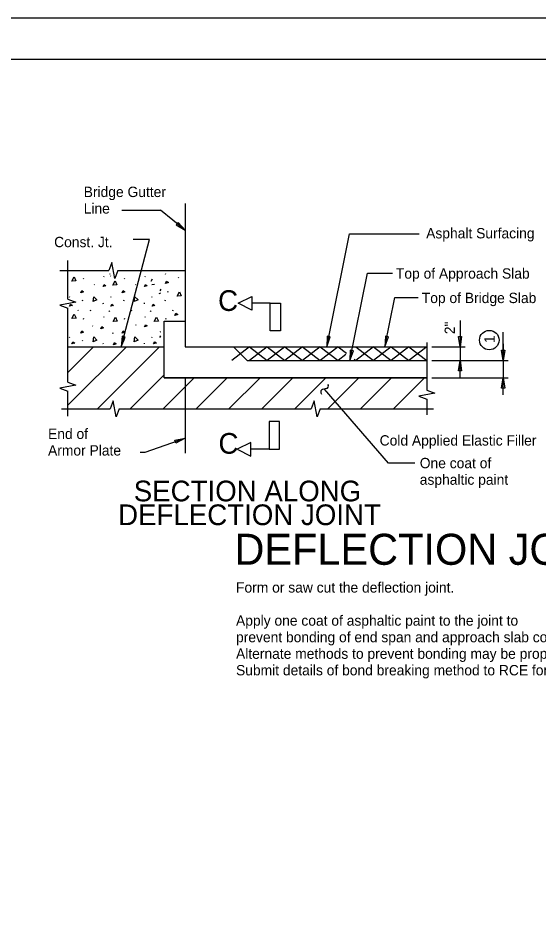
# Model space of a CAD drawing. Extents: x 2799.7 to 2896, y 515.2 to 573.9.
# Drawn here: x 2834.77 to 2851.55, y 544.56 to 573.89 of the extents above; entities that cross this region are included whole.
import ezdxf

# ---------------------------------------------------------------- set-up
doc = ezdxf.new("R2010")
doc.units = 0
for name, color, linetype in [('BR_AUTO DIMENSION', 7, 'Continuous'), ('BR_BORDER LINES', 7, 'Continuous'), ('BR_CONCRETE', 7, 'Continuous'), ('BR_DETAILS', 7, 'Continuous'), ('BR_STRUCTURAL STEEL', 7, 'Continuous'), ('BR_TABLE LINES', 7, 'Continuous'), ('BR_TEXT', 7, 'Continuous'), ('Level 31', 7, 'Continuous')]:
    doc.layers.add(name, color=color, linetype=linetype)

msp = doc.modelspace()

# ---------------------------------------------------------------- linework, layer by layer
at = {"layer": 'BR_AUTO DIMENSION'}
for p, q in [((2840.156, 567.916), (2840.156, 564.596)), ((2838.111, 567.706), (2839.357, 567.706)), ((2840.156, 567.064), (2839.357, 567.706)), ((2838.093, 563.308), (2839.001, 566.763)), ((2839.001, 566.763), (2838.48, 566.763)), ((2844.718, 563.308), (2845.457, 566.948)), ((2845.457, 566.948), (2847.698, 566.948)), ((2845.462, 562.863), (2846.034, 565.678)), ((2846.034, 565.678), (2846.836, 565.678)), ((2846.595, 563.308), (2846.917, 564.891)), ((2846.917, 564.891), (2847.661, 564.891)), ((2849.018, 564.147), (2849.018, 563.308)), ((2849.018, 563.841), (2849.018, 563.308)), ((2850.405, 562.863), (2850.405, 563.774)), ((2848.108, 563.308), (2849.185, 563.308)), ((2849.018, 563.308), (2849.018, 562.863)), ((2850.405, 563.396), (2850.405, 562.863)), ((2848.108, 562.863), (2850.572, 562.863)), ((2848.108, 562.863), (2849.185, 562.863)), ((2849.018, 562.33), (2849.018, 562.863)), ((2850.405, 562.863), (2850.405, 562.308)), ((2844.753, 562.105), (2844.768, 562.074)), ((2848.108, 562.308), (2850.572, 562.308)), ((2850.405, 561.762), (2850.405, 562.308)), ((2850.405, 561.774), (2850.405, 562.308)), ((2844.533, 561.824), (2844.551, 561.782)), ((2844.712, 561.961), (2844.58, 561.924)), ((2846.705, 559.554), (2844.646, 561.943)), ((2838.865, 559.908), (2840.156, 560.359)), ((2838.707, 559.908), (2838.865, 559.908)), ((2847.556, 559.554), (2846.705, 559.554))]:
    msp.add_line(p, q, dxfattribs=at)
for points in [[(2839.865, 567.234), (2840.156, 567.064), (2839.928, 567.312)], [(2838.126, 563.643), (2838.093, 563.308), (2838.223, 563.619)], [(2844.735, 563.644), (2844.718, 563.308), (2844.833, 563.624)], [(2846.613, 563.644), (2846.595, 563.308), (2846.711, 563.624)], [(2849.068, 563.641), (2849.018, 563.308), (2848.968, 563.641)], [(2845.479, 563.2), (2845.462, 562.863), (2845.577, 563.18)], [(2850.455, 563.196), (2850.405, 562.863), (2850.355, 563.196)], [(2848.968, 562.53), (2849.018, 562.863), (2849.068, 562.53)], [(2850.355, 561.974), (2850.405, 562.308), (2850.455, 561.974)], [(2839.825, 560.296), (2840.156, 560.359), (2839.858, 560.202)]]:
    msp.add_lwpolyline(points, close=True, dxfattribs=at)
msp.add_circle((2849.958, 563.521), 0.314, dxfattribs=at)
for centre, radius, start, end in [((2844.7, 562.037), 0.077, 279.0173, 28.8161), ((2844.593, 561.858), 0.0684, 101.4621, 209.7477)]:
    msp.add_arc(centre, radius, start, end, dxfattribs=at)
at = {"layer": 'BR_BORDER LINES'}
msp.add_line((2894.359, 572.556), (2804.582, 572.556), dxfattribs=at)
at = {"layer": 'BR_CONCRETE'}
for p, q in [((2839.48, 564.132), (2840.156, 564.132)), ((2836.378, 563.308), (2839.48, 563.308)), ((2840.156, 563.308), (2847.941, 563.308)), ((2839.48, 562.308), (2847.941, 562.308))]:
    msp.add_line(p, q, dxfattribs=at)
msp.add_lwpolyline([(2840.156, 565.763), (2840.156, 564.132), (2840.156, 563.308)], dxfattribs=at)
at = {"layer": 'BR_DETAILS'}
for p, q in [((2836.121, 565.763), (2837.691, 565.763)), ((2836.378, 565.756), (2836.389, 565.74)), ((2837.533, 565.557), (2837.544, 565.582)), ((2837.713, 565.664), (2837.725, 565.648)), ((2837.748, 565.596), (2837.759, 565.58)), ((2837.98, 565.763), (2840.156, 565.763)), ((2838.862, 565.557), (2838.873, 565.582)), ((2839.52, 565.641), (2839.532, 565.666)), ((2836.875, 565.493), (2836.886, 565.518)), ((2837.222, 565.315), (2837.233, 565.299)), ((2838.204, 565.493), (2838.215, 565.518)), ((2838.551, 565.315), (2838.562, 565.299)), ((2839.064, 565.418), (2839.105, 565.497)), ((2839.17, 565.313), (2839.082, 565.306)), ((2839.942, 565.527), (2839.953, 565.552)), ((2839.365, 565.029), (2839.311, 565.012)), ((2839.353, 565.109), (2839.38, 565.165)), ((2839.601, 565.069), (2839.612, 565.094)), ((2836.425, 564.902), (2836.437, 564.927)), ((2836.847, 564.788), (2836.858, 564.813)), ((2837.507, 564.718), (2837.51, 564.693)), ((2837.755, 564.902), (2837.766, 564.927)), ((2838.177, 564.788), (2838.188, 564.813)), ((2838.836, 564.718), (2838.839, 564.693)), ((2839.084, 564.902), (2839.095, 564.927)), ((2839.506, 564.788), (2839.517, 564.813)), ((2836.701, 564.494), (2836.712, 564.477)), ((2837.1, 564.466), (2837.111, 564.491)), ((2837.696, 564.466), (2837.708, 564.449)), ((2837.708, 564.46), (2837.719, 564.443)), ((2838.429, 564.466), (2838.44, 564.491)), ((2839.026, 564.466), (2839.037, 564.449)), ((2839.037, 564.46), (2839.048, 564.443)), ((2839.759, 564.466), (2839.77, 564.491)), ((2836.875, 564.197), (2836.886, 564.222)), ((2837.533, 564.26), (2837.544, 564.285)), ((2838.204, 564.197), (2838.215, 564.222)), ((2838.862, 564.26), (2838.873, 564.285)), ((2839.534, 564.197), (2839.545, 564.222)), ((2837.173, 563.982), (2837.184, 563.965)), ((2838.551, 564.019), (2838.562, 564.002)), ((2836.425, 563.605), (2836.437, 563.63)), ((2836.847, 563.492), (2836.858, 563.517)), ((2837.822, 563.738), (2837.834, 563.763)), ((2838.177, 563.492), (2838.188, 563.517)), ((2839.084, 563.605), (2839.095, 563.63)), ((2839.365, 563.788), (2839.336, 563.779)), ((2839.342, 563.599), (2839.37, 563.659)), ((2838.265, 563.308), (2836.378, 561.421)), ((2837.204, 563.308), (2836.378, 562.482)), ((2839.325, 563.308), (2837.325, 561.307)), ((2837.507, 563.422), (2837.51, 563.397)), ((2838.836, 563.422), (2838.839, 563.397)), ((2847.941, 563.445), (2847.941, 561.91)), ((2839.48, 562.401), (2838.386, 561.307)), ((2840.447, 562.308), (2839.447, 561.307)), ((2841.507, 562.308), (2840.507, 561.307)), ((2842.568, 562.308), (2841.568, 561.307)), ((2843.629, 562.308), (2842.629, 561.307)), ((2844.69, 562.308), (2843.69, 561.307)), ((2845.75, 562.308), (2844.75, 561.307)), ((2846.811, 562.308), (2845.811, 561.307)), ((2847.872, 562.308), (2846.872, 561.307)), ((2847.941, 561.621), (2847.941, 561.108)), ((2836.166, 561.307), (2837.737, 561.307)), ((2838.026, 561.307), (2844.222, 561.307)), ((2844.511, 561.307), (2848.16, 561.307))]:
    msp.add_line(p, q, dxfattribs=at)
for points in [[(2836.378, 564.842), (2836.378, 566.086)], [(2837.98, 565.763), (2837.884, 565.505), (2837.788, 566.02), (2837.691, 565.763)], [(2836.5, 565.418), (2836.575, 565.56), (2836.634, 565.429), (2836.503, 565.418)], [(2837.513, 565.243), (2837.547, 565.313), (2837.602, 565.271), (2837.513, 565.243)], [(2837.824, 565.289), (2837.899, 565.43), (2837.958, 565.3), (2837.827, 565.289)], [(2838.843, 565.243), (2838.876, 565.313), (2838.931, 565.271), (2838.843, 565.243)], [(2839.526, 565.349), (2839.559, 565.419), (2839.615, 565.377), (2839.526, 565.349)], [(2836.792, 565.045), (2836.826, 565.114), (2836.881, 565.073), (2836.792, 565.045)], [(2838.122, 565.045), (2838.155, 565.114), (2838.21, 565.073), (2838.122, 565.045)], [(2839.898, 564.931), (2839.973, 565.072), (2840.031, 564.942), (2839.9, 564.931)], [(2836.378, 564.842), (2836.635, 564.746), (2836.121, 564.649), (2836.378, 564.553)], [(2836.431, 564.61), (2836.464, 564.68), (2836.52, 564.638), (2836.431, 564.61)], [(2837.185, 564.759), (2837.207, 564.918), (2837.306, 564.815), (2837.187, 564.76)], [(2837.76, 564.61), (2837.794, 564.68), (2837.849, 564.638), (2837.76, 564.61)], [(2838.514, 564.759), (2838.536, 564.918), (2838.636, 564.815), (2838.517, 564.76)], [(2839.09, 564.61), (2839.123, 564.68), (2839.178, 564.638), (2839.09, 564.61)], [(2836.378, 562.163), (2836.378, 564.553)], [(2839.826, 564.317), (2839.859, 564.386), (2839.914, 564.344), (2839.826, 564.317)], [(2836.506, 564.212), (2836.581, 564.353), (2836.639, 564.223), (2836.509, 564.212)], [(2837.83, 564.122), (2837.905, 564.263), (2837.963, 564.133), (2837.832, 564.122)], [(2839.159, 564.122), (2839.234, 564.263), (2839.292, 564.133), (2839.162, 564.122)], [(2836.792, 563.748), (2836.826, 563.818), (2836.881, 563.776), (2836.792, 563.748)], [(2837.434, 563.886), (2837.467, 563.955), (2837.523, 563.914), (2837.434, 563.886)], [(2838.122, 563.748), (2838.155, 563.818), (2838.21, 563.776), (2838.122, 563.748)], [(2838.843, 563.947), (2838.876, 564.016), (2838.931, 563.975), (2838.843, 563.947)], [(2837.185, 563.463), (2837.207, 563.622), (2837.306, 563.519), (2837.187, 563.464)], [(2838.514, 563.463), (2838.536, 563.622), (2838.636, 563.519), (2838.517, 563.464)], [(2836.506, 563.398), (2836.539, 563.468), (2836.595, 563.426), (2836.506, 563.398)], [(2837.841, 563.369), (2837.874, 563.439), (2837.93, 563.397), (2837.841, 563.369)], [(2839.14, 563.396), (2839.173, 563.466), (2839.228, 563.424), (2839.14, 563.396)], [(2836.378, 562.163), (2836.635, 562.067), (2836.121, 561.97), (2836.378, 561.874)], [(2836.378, 561.067), (2836.378, 561.874)], [(2847.941, 561.91), (2848.198, 561.814), (2847.684, 561.717), (2847.941, 561.621)], [(2838.026, 561.307), (2837.93, 561.05), (2837.833, 561.565), (2837.737, 561.307)], [(2844.511, 561.307), (2844.415, 561.05), (2844.318, 561.565), (2844.222, 561.307)]]:
    msp.add_lwpolyline(points, dxfattribs=at)
at = {"layer": 'BR_STRUCTURAL STEEL'}
msp.add_line((2840.156, 562.308), (2840.156, 559.873), dxfattribs=at)
at = {"layer": 'BR_TABLE LINES'}
for p, q in [((2842.9, 564.707), (2842.307, 564.707)), ((2842.226, 563.308), (2841.655, 562.863)), ((2842.226, 563.308), (2842.798, 562.863)), ((2842.798, 563.308), (2842.226, 562.863)), ((2843.369, 563.308), (2842.798, 562.863)), ((2842.798, 563.308), (2843.369, 562.863)), ((2843.369, 563.308), (2843.941, 562.863)), ((2843.941, 563.308), (2843.369, 562.863)), ((2844.512, 563.308), (2843.941, 562.863)), ((2843.941, 563.308), (2844.512, 562.863)), ((2844.512, 563.308), (2845.084, 562.863)), ((2845.084, 563.308), (2844.512, 562.863)), ((2845.084, 563.308), (2845.354, 563.097)), ((2845.655, 563.308), (2846.226, 562.863)), ((2846.226, 563.308), (2845.655, 562.863)), ((2845.655, 563.308), (2845.655, 563.308)), ((2846.798, 563.308), (2846.226, 562.863)), ((2846.226, 563.308), (2846.798, 562.863)), ((2846.798, 563.308), (2847.369, 562.863)), ((2847.369, 563.308), (2846.798, 562.863)), ((2847.941, 563.308), (2847.369, 562.863)), ((2847.369, 563.308), (2847.941, 562.863)), ((2845.331, 563.056), (2845.084, 562.863)), ((2845.603, 562.904), (2845.655, 562.863)), ((2842.866, 560.004), (2842.274, 560.004))]:
    msp.add_line(p, q, dxfattribs=at)
for points in [[(2842.307, 564.484), (2841.863, 564.707), (2842.307, 564.929)], [(2843.226, 563.818), (2842.9, 563.818), (2842.9, 564.707), (2843.226, 564.707)], [(2839.48, 564.132), (2840.156, 564.132), (2840.156, 563.308), (2841.712, 563.308), (2842.156, 562.863), (2847.941, 562.863), (2847.941, 562.308), (2839.48, 562.308)], [(2843.192, 560.893), (2842.866, 560.893), (2842.866, 560.004), (2843.192, 560.004)], [(2842.274, 560.226), (2841.829, 560.004), (2842.274, 559.782)]]:
    msp.add_lwpolyline(points, close=True, dxfattribs=at)
at = {"layer": 'Level 31'}
msp.add_lwpolyline([(2799.693, 515.223), (2895.694, 515.223), (2895.694, 573.89), (2799.693, 573.89)], close=True, dxfattribs=at)

# ---------------------------------------------------------------- texts
at = {"layer": 'BR_AUTO DIMENSION'}
msp.add_text('2"', height=0.3334, rotation=90, dxfattribs=at).set_placement((2848.852, 563.711))
at = {"layer": 'BR_TEXT'}
for s, height, p in [('Bridge Gutter', 0.33332, (2836.885, 568.129)), ('Line', 0.3333, (2836.885, 567.596)), ('Asphalt Surfacing', 0.33332, (2847.924, 566.797)), ('Const. Jt.', 0.3333, (2835.932, 566.514)), ('Top of Approach Slab', 0.33332, (2846.949, 565.5)), ('C', 0.667, (2841.216, 564.46)), ('Top of Bridge Slab', 0.33332, (2847.783, 564.713)), ('End of', 0.3333, (2835.736, 560.335)), ('C', 0.667, (2841.23, 559.86)), ('Cold Applied Elastic Filler', 0.33332, (2846.425, 560.123)), ('Armor Plate', 0.33332, (2835.736, 559.802)), ('One coat of', 0.33332, (2847.718, 559.393)), ('asphaltic paint', 0.33332, (2847.718, 558.86)), ('SECTION ALONG', 0.66673, (2838.498, 558.326)), ('DEFLECTION JOINT', 0.66673, (2837.994, 557.56)), ('DEFLECTION JOINT DETAIL', 1.00005, (2841.744, 556.282)), ('Form or saw cut the deflection joint.', 0.33332, (2841.795, 555.387)), ('Apply one coat of asphaltic paint to the joint to', 0.33332, (2841.795, 554.32)), ('prevent bonding of end span and approach slab concrete.', 0.33332, (2841.795, 553.787)), ('Alternate methods to prevent bonding may be proposed.', 0.33332, (2841.795, 553.253)), ('Submit details of bond breaking method to RCE for approval.', 0.33332, (2841.795, 552.72))]:
    msp.add_text(s, height=height, dxfattribs=at).set_placement(p)
msp.add_text('1', height=0.333, rotation=90, dxfattribs=at).set_placement((2850.132, 563.424))

doc.saveas('drawing.dxf')
